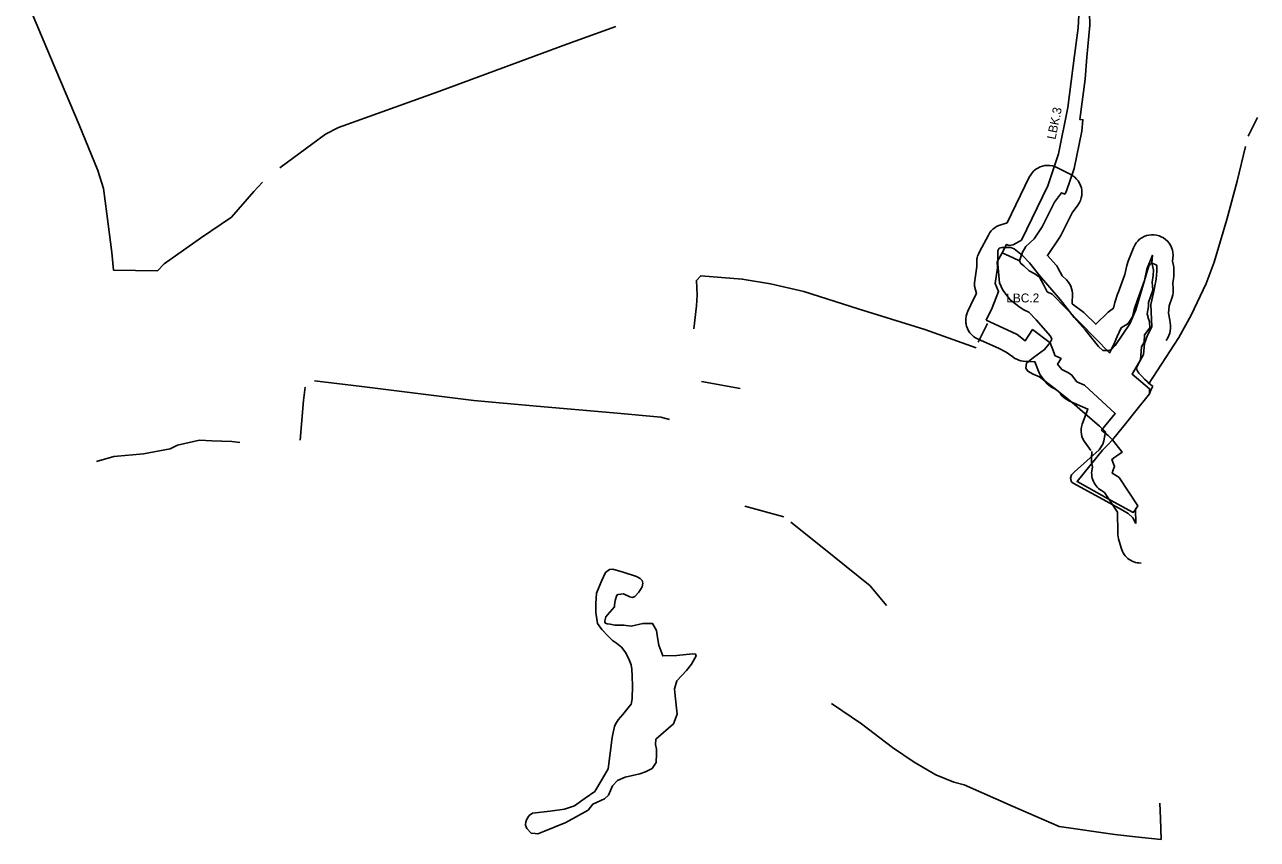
# Model space of a CAD drawing. Extents: x -555426 to -553015, y -1186745 to -1182595.
# Drawn here: x -555096 to -553293, y -1184736 to -1183544 of the extents above; entities that cross this region are included whole.
import ezdxf

# ---------------------------------------------------------------- set-up
doc = ezdxf.new("R2010")
doc.units = 0
for name, color, linetype in [('Level 12', 7, 'Continuous'), ('Level 14', 7, 'Continuous'), ('Level 51', 7, 'Continuous'), ('Level 7', 7, 'Continuous'), ('svahove_deformace', 7, 'Continuous'), ('USES_ID', 7, 'Continuous'), ('USES_LBC_stav', 7, 'Continuous'), ('USES_LBK_stav', 7, 'Continuous')]:
    doc.layers.add(name, color=color, linetype=linetype)

msp = doc.modelspace()

# ---------------------------------------------------------------- linework, layer by layer
at = {"layer": 'Level 12'}
for points in [[(-553640.7, -1183889.3), (-553636.9, -1183877.4), (-553631.4, -1183868.6), (-553619.4, -1183857.3), (-553607.6, -1183839.4), (-553589.5, -1183803.3), (-553579.5, -1183789.6), (-553574.7, -1183791.6), (-553572.6, -1183788.5), (-553560.8, -1183754.2), (-553549.5, -1183699.6), (-553548.2, -1183682.9), (-553552.6, -1183682.5), (-553545, -1183623.5), (-553542.6, -1183591.2), (-553538.2, -1183544.3), (-553538.9, -1183507)], [(-553553.4, -1183520.3), (-553555, -1183548.1), (-553560.5, -1183589), (-553570, -1183665.1), (-553583.9, -1183732.9), (-553598.7, -1183776.5), (-553599.3, -1183779.6), (-553638.1, -1183859.2), (-553650.2, -1183865.8), (-553656, -1183866.8), (-553659.7, -1183865.2), (-553666.3, -1183877.6)]]:
    msp.add_lwpolyline(points, dxfattribs=at)
at = {"layer": 'Level 14'}
for points in [[(-553504.9, -1184151.4), (-553484.1, -1184125.6), (-553472.5, -1184111.2), (-553450.6, -1184083.8), (-553450.8, -1184076.9), (-553476.3, -1184055.3), (-553463.7, -1184034.2), (-553462.3, -1184015.3), (-553458.7, -1184008.3), (-553458.2, -1183997.8), (-553450, -1183987.6), (-553450.9, -1183978.2), (-553452, -1183974.2), (-553454, -1183966.9), (-553452.1, -1183956.2), (-553452, -1183950.1), (-553445.8, -1183932.3), (-553446.7, -1183920.6), (-553445.2, -1183910.6), (-553444.8, -1183902.9), (-553446.4, -1183896), (-553447.5, -1183892.1), (-553446.1, -1183881.1), (-553454.6, -1183901.7), (-553458.1, -1183917.9), (-553468.3, -1183946.2), (-553473.1, -1183960.5), (-553475.4, -1183971.5), (-553481.7, -1183981), (-553492.3, -1183987.4), (-553498.1, -1184000.3), (-553503.5, -1184012.7), (-553509.4, -1184024.1), (-553593.3, -1183938.2), (-553600.5, -1183934.5), (-553606, -1183923.8), (-553611.6, -1183913.2), (-553618.7, -1183908.6), (-553626.7, -1183904.1), (-553634, -1183897.1), (-553634.7, -1183896.6), (-553638.9, -1183893.4), (-553640.7, -1183889.3), (-553650.2, -1183885.2), (-553666.3, -1183877.6), (-553673.4, -1183890.9), (-553673.2, -1183899.7), (-553676.7, -1183922.7), (-553671.5, -1183934.4), (-553681.1, -1183958.1), (-553689.7, -1183976.3)], [(-553689.7, -1183976.3), (-553658.7, -1183990.2), (-553644.5, -1183997.2), (-553632.4, -1184006.2), (-553621.8, -1183990), (-553596, -1184009.6), (-553590.1, -1184024.6), (-553589.1, -1184028.1), (-553580.1, -1184032.4), (-553585.2, -1184040.5), (-553578.8, -1184048.5), (-553576, -1184050), (-553570.4, -1184053), (-553564.7, -1184056), (-553556.9, -1184066.3), (-553545.6, -1184071.4), (-553500.7, -1184112.8), (-553520.9, -1184137.3), (-553517.9, -1184139.7), (-553511.3, -1184145.2), (-553504.9, -1184151.4), (-553511.7, -1184158.6), (-553515.5, -1184162.7), (-553519.3, -1184166.4), (-553556.7, -1184212.5), (-553527.8, -1184228.5), (-553512.1, -1184237.2), (-553481.1, -1184254.2), (-553474.5, -1184257.6), (-553473.7, -1184256.4), (-553472.7, -1184255.4), (-553471.2, -1184253.1), (-553467.8, -1184248), (-553495.1, -1184206.4), (-553498.1, -1184204.5), (-553505.4, -1184200), (-553503.8, -1184195.4), (-553501.8, -1184190.2), (-553505.8, -1184180), (-553501.2, -1184176.9), (-553496.8, -1184173.6), (-553490.7, -1184169.4), (-553504.9, -1184151.4)]]:
    msp.add_lwpolyline(points, dxfattribs=at)
at = {"layer": 'Level 51'}
for points in [[(-555096.3, -1183500.7), (-555050.6, -1183609.8), (-555016.3, -1183690.4), (-554989.4, -1183757.1), (-554981.1, -1183783.3), (-554976, -1183820.6), (-554968.5, -1183877.2), (-554966.4, -1183902.9), (-554901.8, -1183903.8), (-554892.3, -1183893.6), (-554839.2, -1183856.1), (-554793.9, -1183825.4), (-554761, -1183788.1), (-554748.1, -1183774.1)], [(-554722.9, -1183753.3), (-554656.1, -1183703.9), (-554637, -1183694.2), (-554490.5, -1183641.7), (-554303.2, -1183572.4), (-554231.3, -1183546.2)], [(-553306.2, -1183707), (-553292.9, -1183679.5)], [(-553452.3, -1184069.8), (-553407.7, -1184001.4), (-553389.7, -1183968.9), (-553368, -1183922.6), (-553356, -1183891.2), (-553337.8, -1183828.7), (-553322.7, -1183772.8), (-553310.1, -1183722.1)], [(-554117.3, -1183988.9), (-554113.3, -1183955.4), (-554112.5, -1183939.4), (-554113.5, -1183918.1), (-554107.2, -1183911.2), (-554046.5, -1183916.1), (-554005.2, -1183923.1), (-553956.2, -1183934.2), (-553877, -1183959.6), (-553779.2, -1183989.7), (-553704.3, -1184016.6)], [(-553701.4, -1184008.3), (-553687.7, -1183981.3)], [(-554693.2, -1184151.9), (-554688.1, -1184093.8), (-554685.8, -1184074.2)], [(-554672.4, -1184064.8), (-554602.8, -1184073.5), (-554509.6, -1184085.2), (-554439.1, -1184093.6), (-554347.3, -1184101.9), (-554234.9, -1184111.9), (-554165.8, -1184118.4), (-554152.8, -1184121.8)], [(-554106.1, -1184065.9), (-554049.4, -1184076.1)], [(-554991.3, -1184183.1), (-554965.9, -1184175.9), (-554922.3, -1184171.8), (-554883.4, -1184164.4), (-554872.5, -1184158.9), (-554840.3, -1184151.8), (-554822.6, -1184153), (-554793, -1184154), (-554781.3, -1184155)], [(-554042.8, -1184248.4), (-553985.8, -1184263.9)], [(-553975.3, -1184271.9), (-553929.5, -1184308.2), (-553859.5, -1184365.2), (-553835.3, -1184393.6)], [(-553916, -1184537), (-553872, -1184567.2), (-553826.6, -1184601.6), (-553794.8, -1184623.2), (-553763.4, -1184641.7), (-553737, -1184652.4), (-553722, -1184656.4), (-553650.3, -1184688), (-553583.1, -1184717.1), (-553501.5, -1184728.8), (-553471, -1184732.6), (-553433.7, -1184736.1), (-553434.7, -1184705.8), (-553435.5, -1184683.3)]]:
    msp.add_lwpolyline(points, dxfattribs=at)
at = {"layer": 'Level 7'}
for points in [[(-553703.1, -1183886.5), (-553702.2, -1183882.5), (-553701.1, -1183879.6), (-553699.6, -1183876.3), (-553686.4, -1183851.6), (-553684.3, -1183848.1), (-553682.2, -1183845.5), (-553679.8, -1183843.1), (-553677.2, -1183840.9), (-553674.3, -1183839.2), (-553671.3, -1183837.7), (-553659, -1183833.6), (-553626.6, -1183767), (-553624.5, -1183763.3), (-553622.3, -1183760.4), (-553619.8, -1183757.7), (-553617, -1183755.4), (-553613.9, -1183753.5), (-553610.6, -1183751.9), (-553607.2, -1183750.7), (-553603.6, -1183750), (-553599.9, -1183749.7), (-553596.3, -1183749.8), (-553592.7, -1183750.4), (-553589.2, -1183751.4), (-553585.3, -1183753.1), (-553566.6, -1183762.6), (-553562.8, -1183764.7), (-553559.9, -1183767), (-553557.3, -1183769.6), (-553555, -1183772.5), (-553553, -1183775.7), (-553551.5, -1183779), (-553550.4, -1183782.6), (-553549.8, -1183786.2), (-553549.6, -1183789.9), (-553549.8, -1183793.6), (-553550.6, -1183797.2), (-553551.7, -1183800.8), (-553553.3, -1183804.1), (-553555.6, -1183807.8), (-553563.7, -1183818.9), (-553580.5, -1183852.3), (-553582.8, -1183856.4), (-553600.1, -1183881.6), (-553587.2, -1183895.5), (-553586.2, -1183896.9), (-553584.9, -1183899.4), (-553578.6, -1183911.5), (-553572, -1183917.2), (-553569.6, -1183920), (-553567.5, -1183923), (-553565.9, -1183926.3), (-553564.6, -1183929.7), (-553563.8, -1183933.3), (-553563.5, -1183936.9), (-553564, -1183952.2), (-553546.9, -1183965.1), (-553545.8, -1183965.9), (-553529.3, -1183982.2), (-553511.4, -1183964.4), (-553503.6, -1183958.8), (-553501.4, -1183950.5), (-553496.8, -1183936.8), (-553496.5, -1183936), (-553487, -1183909.5), (-553484, -1183896.1), (-553482, -1183889.6), (-553474.2, -1183870.3), (-553472.3, -1183866.4), (-553470.2, -1183863.2), (-553467.8, -1183860.4), (-553465.1, -1183857.8), (-553462, -1183855.7), (-553458.7, -1183853.9), (-553455.2, -1183852.5), (-553451.6, -1183851.6), (-553447.9, -1183851.2), (-553444.2, -1183851.2), (-553440.5, -1183851.7), (-553436.8, -1183852.6), (-553433.4, -1183854), (-553430.1, -1183855.8), (-553427.1, -1183858), (-553424.3, -1183860.5), (-553421.9, -1183863.4), (-553419.9, -1183866.6), (-553418.3, -1183870), (-553417.2, -1183873.5), (-553416.4, -1183877.2), (-553416.2, -1183880.9), (-553416.4, -1183885.3), (-553417, -1183889.9), (-553415.7, -1183896), (-553415.1, -1183899.1), (-553414.9, -1183901.8), (-553414.9, -1183904.9), (-553415.3, -1183911.6), (-553415.6, -1183915.5), (-553416.5, -1183921.5), (-553415.9, -1183930.1)], [(-553719.1, -1183982.6), (-553719.6, -1183977.7), (-553719.6, -1183974), (-553719.1, -1183970.4), (-553718.1, -1183966.9), (-553716.5, -1183962.9), (-553708.3, -1183945.6), (-553703.8, -1183937), (-553706.5, -1183926.2), (-553706.8, -1183923.8), (-553706.8, -1183921.5), (-553706.3, -1183918.1), (-553703.3, -1183897.8), (-553703.4, -1183892.1), (-553703.3, -1183888.5), (-553702.7, -1183884.4)], [(-553416, -1183929.1), (-553415.9, -1183933.1), (-553416.1, -1183936.2), (-553416.7, -1183939.2), (-553417.7, -1183942.6), (-553422.1, -1183955.4), (-553422.9, -1183965.8), (-553420.9, -1183976.1), (-553420.2, -1183984.1), (-553420, -1183988.3), (-553420.3, -1183991.9), (-553421, -1183995.4), (-553422.2, -1183998.8), (-553423.7, -1184002), (-553426.3, -1184006.1)], [(-553536.7, -1184166.9), (-553546.4, -1184153.1), (-553548.2, -1184149.9), (-553549.5, -1184146.5), (-553550.3, -1184143), (-553550.8, -1184139.4), (-553550.8, -1184135.8), (-553550.3, -1184132.2), (-553549.4, -1184128.6), (-553540.8, -1184106.3), (-553568.5, -1184094.1), (-553571.7, -1184092.5), (-553574.3, -1184090.8), (-553576.7, -1184088.9), (-553578.8, -1184086.8), (-553581.1, -1184084.1), (-553584.7, -1184079.4), (-553590.2, -1184076.4), (-553592.6, -1184075.2), (-553595.6, -1184073.3), (-553598, -1184071.5), (-553600.3, -1184069.4), (-553602.6, -1184066.8), (-553608.3, -1184059.6), (-553610.6, -1184056.4), (-553612.1, -1184053.5), (-553618.3, -1184037), (-553635.6, -1184036.1), (-553638.7, -1184035.5), (-553641.8, -1184034.7), (-553644.7, -1184033.5), (-553647.6, -1184032.1), (-553650.7, -1184030), (-553660.2, -1184022.9), (-553671.5, -1184017.3), (-553701.4, -1184003.9), (-553705.2, -1184001.9), (-553708.2, -1183999.9), (-553711, -1183997.4), (-553713.4, -1183994.7), (-553715.4, -1183991.6), (-553717.1, -1183988.4), (-553718.4, -1183984.9), (-553719.5, -1183980.2)], [(-553462.7, -1184331.8), (-553466.1, -1184331.6), (-553468.7, -1184331.3), (-553471.2, -1184330.7), (-553473.6, -1184329.9), (-553476, -1184328.9), (-553478.3, -1184327.7), (-553480.4, -1184326.3), (-553482.5, -1184324.8), (-553484.4, -1184323), (-553486.1, -1184321.1), (-553487.7, -1184319.1), (-553489.1, -1184316.9), (-553490.3, -1184314.7), (-553491.3, -1184312.3), (-553492.2, -1184309.5), (-553496, -1184296), (-553496.7, -1184293.1), (-553497, -1184290.5), (-553497.2, -1184287.5), (-553497.7, -1184257.2), (-553516.6, -1184228.3), (-553520.9, -1184225.7), (-553523.3, -1184224), (-553525.3, -1184222.4), (-553527.1, -1184220.6), (-553528.8, -1184218.7), (-553530.3, -1184216.6), (-553531.6, -1184214.4), (-553532.8, -1184212.2), (-553533.7, -1184209.8), (-553534.4, -1184207.3), (-553535, -1184204.8), (-553535.3, -1184202.3), (-553535.4, -1184199.7), (-553535.2, -1184197.2), (-553534.3, -1184190.7), (-553535.5, -1184184.1), (-553535.8, -1184181.4), (-553535.8, -1184178.8), (-553534.9, -1184168.4)]]:
    msp.add_lwpolyline(points, dxfattribs=at)
at = {"layer": 'svahove_deformace'}
msp.add_line((-553445.9, -1184073.3), (-553458.2, -1184062.4), dxfattribs=at)
for points in [[(-553458.2, -1184062.4), (-553462, -1184058), (-553466.4, -1184053.6), (-553468.9, -1184050.1), (-553469.9, -1184046), (-553467.3, -1184040.7), (-553459.5, -1184026.2), (-553458.2, -1184010.1), (-553453.8, -1183998.1), (-553447.5, -1183985.8), (-553448.7, -1183953.3), (-553444.9, -1183936.3), (-553441.2, -1183916.1), (-553440.2, -1183904.4), (-553439.9, -1183896.5), (-553441.2, -1183895.2), (-553443.4, -1183894), (-553445.9, -1183893.4), (-553448.7, -1183893.4), (-553451.6, -1183896.5), (-553470.5, -1183961.2), (-553479.6, -1183981.7), (-553500.8, -1184013.5), (-553506.8, -1184019.5), (-553512.1, -1184020.5), (-553518.8, -1184020.5), (-553525.1, -1184014.8), (-553544.6, -1183990.2), (-553560.7, -1183972.2), (-553581.2, -1183945.7), (-553611.8, -1183910.7), (-553626.3, -1183892.4), (-553636.7, -1183881.7), (-553648.7, -1183871.9), (-553653.8, -1183870), (-553662, -1183869.7), (-553666.7, -1183869.7), (-553670.5, -1183871), (-553672.4, -1183874.7), (-553672.4, -1183894), (-553670.2, -1183921.4), (-553665.4, -1183932.5), (-553654.7, -1183946.3), (-553639.9, -1183957.7), (-553634.5, -1183960.9), (-553627.3, -1183964.6), (-553616.6, -1183975.7), (-553595.7, -1183999.7), (-553593.8, -1184003.8), (-553596, -1184008.8), (-553604.2, -1184019.2), (-553620.3, -1184030.9), (-553630.7, -1184039.1), (-553631.4, -1184046.3), (-553628.5, -1184050.8), (-553621, -1184055.2), (-553611.8, -1184059.3), (-553588.8, -1184076.9), (-553563.6, -1184096.5), (-553545.3, -1184112.6), (-553523.8, -1184131.5), (-553515, -1184139.7), (-553517.5, -1184153), (-553518.8, -1184157.7), (-553524.4, -1184165.9), (-553560.4, -1184198.1), (-553564.8, -1184202.8), (-553566.4, -1184207.5), (-553564.8, -1184212.9), (-553562.3, -1184214.8), (-553523.8, -1184235.9), (-553490.1, -1184254.5), (-553481.9, -1184259.3), (-553474.9, -1184265.3), (-553470.8, -1184273.8)], [(-553470.8, -1184273.8), (-553471, -1184252.9), (-553467.8, -1184248), (-553495.1, -1184206.4), (-553498.1, -1184204.5), (-553505.4, -1184200), (-553503.8, -1184195.4), (-553501.8, -1184190.2), (-553505.8, -1184180), (-553501.2, -1184176.9), (-553496.8, -1184173.6), (-553490.7, -1184169.4), (-553504.9, -1184151.4), (-553484.1, -1184125.6), (-553472.5, -1184111.2), (-553450.6, -1184083.8), (-553448.5, -1184077.2), (-553445.9, -1184073.3)], [(-554193.1, -1184366.3), (-554192, -1184361), (-554192.9, -1184357.2), (-554195.9, -1184354.3), (-554201.1, -1184351.5), (-554220.9, -1184345.2), (-554235.8, -1184340.6), (-554240.6, -1184341.2), (-554246.5, -1184345.3), (-554252.6, -1184358.2), (-554259.8, -1184375.6), (-554260.8, -1184391.1), (-554260.8, -1184404.1), (-554258.3, -1184420), (-554251.8, -1184428.9), (-554242.7, -1184438.7), (-554236.2, -1184444.9), (-554230.3, -1184449.1), (-554223.1, -1184455), (-554216.9, -1184463), (-554211.8, -1184473.2), (-554209.1, -1184480.7), (-554208.2, -1184487.1), (-554207.4, -1184497.3), (-554207, -1184511.8), (-554207.4, -1184529.9), (-554208.3, -1184536.5), (-554208.8, -1184538), (-554213.6, -1184543.7), (-554221, -1184553.2), (-554227.8, -1184561), (-554231.8, -1184567.4), (-554233.2, -1184571), (-554235.4, -1184579.5), (-554236.7, -1184587.2), (-554242.8, -1184633), (-554251.2, -1184647.9), (-554262, -1184665.8), (-554276.1, -1184676), (-554292, -1184686.8), (-554306.4, -1184692), (-554327.4, -1184694.6), (-554353.1, -1184697.9), (-554358.4, -1184701.4), (-554361.7, -1184706.3), (-554363, -1184710.3), (-554363.4, -1184715.1), (-554361.7, -1184720), (-554355.3, -1184727), (-554349.5, -1184727.3), (-554345.3, -1184727.8), (-554335.8, -1184724.1), (-554304.4, -1184711.2), (-554272, -1184693.5), (-554265.3, -1184684.4), (-554248, -1184676.6), (-554242.1, -1184671.4), (-554236.1, -1184657.9), (-554228.8, -1184650), (-554217.9, -1184645), (-554196.4, -1184640.3), (-554188.2, -1184637.3), (-554178.3, -1184632.3), (-554172.6, -1184623.5), (-554171.7, -1184611.2), (-554172.1, -1184603.9), (-554173.6, -1184597.1), (-554172.8, -1184589.5), (-554146.9, -1184567.1), (-554141.8, -1184553), (-554144.5, -1184525.8), (-554145.5, -1184516), (-554142.1, -1184503.9), (-554128.2, -1184488.8), (-554120.9, -1184479.6), (-554113.9, -1184467.7), (-554114.8, -1184465), (-554119.3, -1184464.4), (-554142.1, -1184466.8), (-554162.9, -1184467.7), (-554168.7, -1184452.1), (-554170.3, -1184440.6), (-554172.1, -1184430.4), (-554177.7, -1184420.3), (-554191.9, -1184420.1), (-554209.1, -1184424.2), (-554219.5, -1184422.7), (-554227.3, -1184422.7), (-554233, -1184422.4), (-554239.9, -1184421), (-554244.2, -1184420.4), (-554246.6, -1184419.8), (-554247.7, -1184418), (-554247.7, -1184416.2), (-554246, -1184410.3), (-554243.8, -1184407.7), (-554233.5, -1184395.6), (-554233.2, -1184393.1), (-554232.4, -1184386.6), (-554230, -1184378.5), (-554228.2, -1184377.9), (-554220.1, -1184376.8), (-554210.9, -1184380.9), (-554206.8, -1184382), (-554203.4, -1184380.8), (-554198, -1184374.1), (-554193.1, -1184366.3)]]:
    msp.add_lwpolyline(points, dxfattribs=at)
at = {"layer": 'USES_LBC_stav'}
for points in [[(-553689.7, -1183976.3), (-553681.1, -1183958.1), (-553671.5, -1183934.4), (-553676.7, -1183922.7), (-553673.2, -1183899.7), (-553673.4, -1183890.9), (-553666.3, -1183877.6), (-553650.2, -1183885.2), (-553640.7, -1183889.3), (-553638.9, -1183893.4), (-553634.7, -1183896.6), (-553634, -1183897.1), (-553626.7, -1183904.1), (-553618.7, -1183908.6), (-553611.6, -1183913.2), (-553606, -1183923.8), (-553600.5, -1183934.5), (-553593.3, -1183938.2), (-553509.4, -1184024.1), (-553503.5, -1184012.7), (-553498.1, -1184000.3), (-553492.3, -1183987.4), (-553481.7, -1183981), (-553475.4, -1183971.5), (-553473.1, -1183960.5), (-553468.3, -1183946.2), (-553458.1, -1183917.9), (-553454.6, -1183901.7), (-553446.1, -1183881.1), (-553447.5, -1183892.1), (-553446.4, -1183896), (-553444.8, -1183902.9), (-553445.2, -1183910.6), (-553446.7, -1183920.6), (-553445.8, -1183932.3), (-553452, -1183950.1), (-553452.1, -1183956.2), (-553454, -1183966.9), (-553452, -1183974.2), (-553450.9, -1183978.2), (-553450, -1183987.6), (-553458.2, -1183997.8), (-553458.7, -1184008.3), (-553462.3, -1184015.3), (-553463.7, -1184034.2), (-553476.3, -1184055.3), (-553450.8, -1184076.9), (-553450.6, -1184083.8), (-553472.5, -1184111.2), (-553484.1, -1184125.6), (-553504.9, -1184151.4)], [(-553504.9, -1184151.4), (-553511.3, -1184145.2), (-553517.9, -1184139.7), (-553520.9, -1184137.3), (-553500.7, -1184112.8), (-553545.6, -1184071.4), (-553556.9, -1184066.3), (-553564.7, -1184056), (-553570.4, -1184053), (-553576, -1184050), (-553578.8, -1184048.5), (-553585.2, -1184040.5), (-553580.1, -1184032.4), (-553589.1, -1184028.1), (-553590.1, -1184024.6), (-553596, -1184009.6), (-553621.8, -1183990), (-553632.4, -1184006.2), (-553644.5, -1183997.2), (-553658.7, -1183990.2), (-553689.7, -1183976.3)]]:
    msp.add_lwpolyline(points, dxfattribs=at)
msp.add_lwpolyline([(-553504.9, -1184151.4), (-553490.7, -1184169.4), (-553496.8, -1184173.6), (-553501.2, -1184176.9), (-553505.8, -1184180), (-553501.8, -1184190.2), (-553503.8, -1184195.4), (-553505.4, -1184200), (-553498.1, -1184204.5), (-553495.1, -1184206.4), (-553467.8, -1184248), (-553471.2, -1184253.1), (-553472.7, -1184255.4), (-553473.7, -1184256.4), (-553474.5, -1184257.6), (-553481.1, -1184254.2), (-553512.1, -1184237.2), (-553527.8, -1184228.5), (-553556.7, -1184212.5), (-553519.3, -1184166.4), (-553515.5, -1184162.7), (-553511.7, -1184158.6), (-553504.9, -1184151.4)], close=True, dxfattribs=at)
at = {"layer": 'USES_LBK_stav'}
for points in [[(-553666.3, -1183877.6), (-553659.7, -1183865.2), (-553656, -1183866.8), (-553650.2, -1183865.8), (-553638.1, -1183859.2), (-553599.3, -1183779.6), (-553598.7, -1183776.5), (-553583.9, -1183732.9), (-553570, -1183665.1), (-553560.5, -1183589), (-553555, -1183548.1), (-553553.4, -1183520.3), (-553552, -1183488.3), (-553551.6, -1183383.7), (-553553.6, -1183376.7)], [(-553538.9, -1183507), (-553538.2, -1183544.3), (-553542.6, -1183591.2), (-553545, -1183623.5), (-553552.6, -1183682.5), (-553548.2, -1183682.9), (-553549.5, -1183699.6), (-553560.8, -1183754.2), (-553572.6, -1183788.5), (-553574.7, -1183791.6), (-553579.5, -1183789.6), (-553589.5, -1183803.3), (-553607.6, -1183839.4), (-553619.4, -1183857.3), (-553631.4, -1183868.6), (-553636.9, -1183877.4), (-553640.7, -1183889.3)], [(-553640.7, -1183889.3), (-553650.2, -1183885.2), (-553666.3, -1183877.6)]]:
    msp.add_lwpolyline(points, dxfattribs=at)

# ---------------------------------------------------------------- texts
at = {"layer": 'USES_ID'}
msp.add_text('LBK.3', height=13, rotation=78.3052, dxfattribs=at).set_placement((-553588.4, -1183712.5))
msp.add_text('LBC.2', height=13, dxfattribs=at).set_placement((-553660.3, -1183950.2))

doc.saveas('drawing.dxf')
